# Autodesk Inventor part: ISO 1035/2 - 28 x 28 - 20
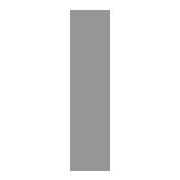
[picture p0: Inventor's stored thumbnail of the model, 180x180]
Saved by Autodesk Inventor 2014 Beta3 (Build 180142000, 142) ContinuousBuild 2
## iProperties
Created: 2010-11
Part Number: ISO 1035/2 - 28 x 28 - 20
Material: Steel, Mild
Description: Hot-rolled steel bars - Part 2: square bars
Document SubType Name: Modeling
Standard: ISO
Designer: Beta-8540w
Standard Revision: First edition 1980-10-15
Standards Organization: ISO
Language: en-US
Size Designation: 28x 28*
Categories: <MemberInstance><Categories><Category DisplayName="Structural Shapes" InternalName="089c4875-fa83-4c05-b084-43b9cc11f5ed" Mnemonic="GRDR"><CategoryParameter Dis
Stock Number: 28x 28*
Density: 7.86 g/cm^3
Appearance: Steel
IsCustomPart: 1
_CCFamilyMember: 180
_CCFamilyDisplayName: ISO 1035/2 - 1980 - Hot-rolled steel bars - Part 2: square bars
_FrameMemberDoc: Frame Member File
_Version: 15.0.0
_GetPNFromCC: 1
G_L: 20.000 mm
G_W: 28.000 mm
G_H: 28.000 mm
Author: Beta-8540w
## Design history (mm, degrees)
node "Start plane"
node "End plane"
sketch "Sketch"
  geometry: L1 (14, -14)-(-14, -14); L2 (-14, -14)-(-14, 14); L3 (-14, 14)-(14, 14); L4 (14, 14)-(14, -14); L5 (-6, 0)-(8, 0); L6 (0, -30)-(0, 40); L7 (0, 54)-(0, -44) reference; L8 (-19.6, 0)-(19.6, 0) reference
  constraints: 12 end point, 2 collinear, 2 parallel, 1 horizontal, 1 perpendicular
  dimensions: "d0" = 28 distance between parallel lines of L3 L1 (= G_W); "d1" = 28 distance between parallel lines of L4 L2 (= G_H); "d4" = 14 distance between parallel lines of L6 L4 (= 0.5 x d1); "d5" = 14 distance between parallel lines of L5 L3 (= 0.5 x d0)
extrude "Body" new body sketch "Sketch" stored distance "d2" = 20 (= G_L); taper "d3" = 0 deg
node "Driven Length"
  sketch "Sketch3"
    geometry: L1 (0, 0)-(10, 0) reference
    constraints: 2 end point, 1 horizontal
  workplane "Work Plane3"
  sketch "Sketch4"
    geometry: L1 (-2, 0)-(12, 0) reference; L2 (-2, 20)-(12, 20) reference
    dimensions: "d9" = 20 distance between parallel lines of L1 L2 (derived)
body "Solid1"
other parameters: "G_W" = 28 [user parameter; used in 1 equation term], "G_H" = 28 [user parameter; used in 1 equation term], "G_L" = 20 (= d9) [user parameter; used in 1 equation term], "G_OFFSET_START" = 0 [user parameter; used in 1 equation term], "G_OFFSET_END" = 0 [user parameter; used in 1 equation term], "d6" = 0 (computed from G_OFFSET_START), "d8" = 90 deg, "AREA" = 78.4 [user parameter]
